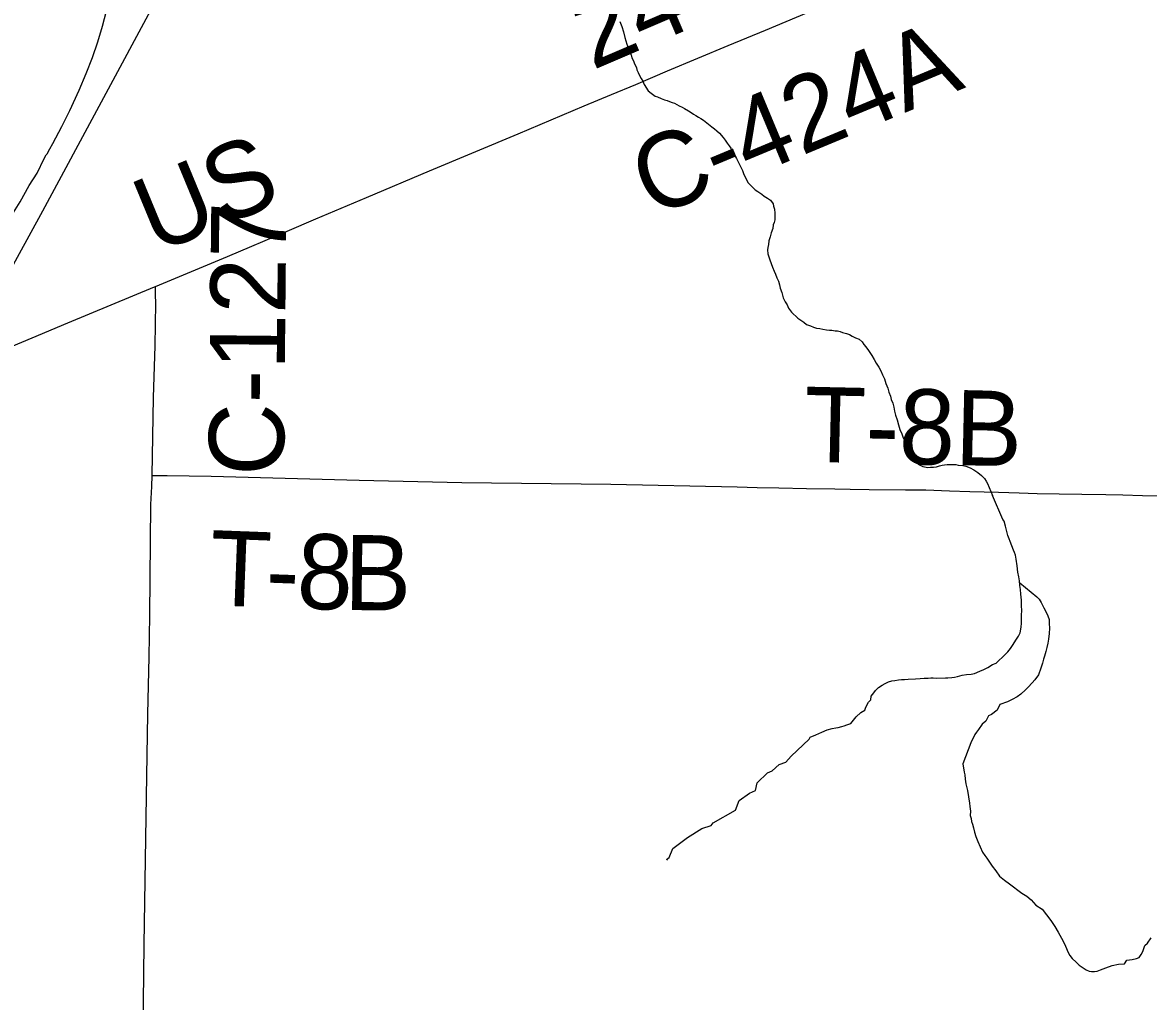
# Model space of a CAD drawing. Extents: x 2.1 to 73.9, y 4 to 26.
# Drawn here: x 44.0631 to 44.4887, y 21.6606 to 22.0307 of the extents above; entities that cross this region are included whole.
import ezdxf

# ---------------------------------------------------------------- set-up
doc = ezdxf.new("R2010")
doc.units = 0
for name, color, linetype in [('GM_X_County_Road', 7, 'Continuous'), ('GM_X_County_Road_Text', 7, 'Continuous'), ('GM_X_Minor_River', 7, 'Continuous'), ('GM_X_Rail_Line', 7, 'Continuous'), ('GM_X_Township_Road', 7, 'Continuous'), ('GM_X_Township_Road_Text', 7, 'Continuous'), ('GM_X_US_Route', 7, 'Continuous')]:
    doc.layers.add(name, color=color, linetype=linetype)

msp = doc.modelspace()

# ---------------------------------------------------------------- linework, layer by layer
at = {"layer": 'GM_X_County_Road'}
for points in [[(44.11329, 21.93085), (44.1405, 21.94215), (44.16309, 21.95176), (44.17395, 21.9564), (44.19313, 21.96454), (44.21691, 21.97456), (44.25046, 21.9886), (44.27537, 21.99911), (44.28569, 22.00344), (44.29488, 22.00725), (44.3069, 22.01234), (44.32983, 22.02197), (44.3439, 22.02781), (44.36339, 22.03597), (44.382, 22.04385), (44.41728, 22.0586), (44.42762, 22.06286), (44.45106, 22.07288), (44.48515, 22.08724), (44.51755, 22.10081), (44.53217, 22.10694), (44.55134, 22.11508), (44.61158, 22.14023), (44.62022, 22.1439)], [(44.02324, 21.90284), (44.02578, 21.90025), (44.02911, 21.89932), (44.03255, 21.89869), (44.03651, 21.89932), (44.03954, 21.89995), (44.055, 21.90649), (44.06674, 21.91144), (44.0802, 21.91713), (44.11294, 21.93071), (44.11329, 21.93085)], [(44.11201, 21.85939), (44.11262, 21.88892), (44.11315, 21.90847), (44.11347, 21.92461), (44.11338, 21.92775), (44.11329, 21.93085)], [(44.10393, 21.3377), (44.10403, 21.34329), (44.10477, 21.39925), (44.10542, 21.4381), (44.10597, 21.48473), (44.10688, 21.54067), (44.10737, 21.57021), (44.10789, 21.60595), (44.10825, 21.63082), (44.10862, 21.64946), (44.10908, 21.6821), (44.10984, 21.73028), (44.11043, 21.76913), (44.11092, 21.79089), (44.1112, 21.80643), (44.11141, 21.8344), (44.11162, 21.84839), (44.11188, 21.8553), (44.11201, 21.85939)]]:
    msp.add_lwpolyline(points, dxfattribs=at)
at = {"layer": 'GM_X_Minor_River'}
for points in [[(44.28889, 22.0311), (44.28962, 22.02919), (44.29016, 22.02709), (44.2907, 22.02499), (44.29142, 22.02251), (44.29197, 22.02117), (44.29252, 22.01964), (44.29307, 22.01849), (44.29343, 22.01735), (44.29398, 22.0162), (44.29435, 22.01505), (44.29508, 22.01371), (44.29526, 22.01276), (44.29582, 22.0118), (44.29618, 22.01084), (44.29692, 22.0095), (44.29748, 22.00854), (44.29803, 22.0072), (44.29951, 22.0049), (44.30064, 22.00393), (44.30214, 22.00277), (44.30309, 22.00256), (44.30441, 22.00197), (44.30573, 22.00138), (44.30668, 22.00118), (44.30762, 22.00078), (44.30857, 22.00039), (44.30952, 22.00018), (44.31121, 21.9992), (44.31235, 21.99861), (44.31329, 21.99822), (44.3148, 21.99725), (44.31574, 21.99666), (44.31668, 21.99608), (44.31762, 21.99549), (44.31856, 21.99491), (44.3195, 21.99432), (44.32045, 21.99373), (44.32232, 21.99219), (44.32364, 21.99121), (44.32458, 21.99044), (44.32552, 21.98966), (44.32646, 21.98889), (44.32795, 21.98716), (44.3287, 21.98619), (44.32944, 21.98504), (44.33018, 21.98408), (44.33074, 21.98312), (44.33129, 21.98197), (44.33203, 21.98082), (44.33296, 21.97928), (44.3337, 21.97775), (44.33444, 21.97622), (44.33517, 21.97469), (44.33572, 21.97316), (44.33738, 21.97009), (44.33888, 21.96855), (44.34, 21.96739), (44.34094, 21.96681), (44.34245, 21.96583), (44.34339, 21.96506), (44.34471, 21.96428), (44.34584, 21.9635), (44.34677, 21.96215), (44.34694, 21.9612), (44.3473, 21.96006), (44.34747, 21.95853), (44.34745, 21.9572), (44.34743, 21.95606), (44.34723, 21.95512), (44.34683, 21.95417), (44.34662, 21.95285), (44.34602, 21.95115), (44.34562, 21.94963), (44.34521, 21.94812), (44.345, 21.94679), (44.3448, 21.94566), (44.34459, 21.94471), (44.34476, 21.94319), (44.34512, 21.94204), (44.34548, 21.94089), (44.34603, 21.93955), (44.34658, 21.93822), (44.34713, 21.93669), (44.34768, 21.93554), (44.34823, 21.9342), (44.34878, 21.93286), (44.34914, 21.93153), (44.3495, 21.93019), (44.35005, 21.92866), (44.35058, 21.92656), (44.35132, 21.92503)], [(44.35132, 21.92503), (44.35206, 21.92388), (44.35261, 21.92273), (44.35373, 21.92119), (44.35617, 21.91887), (44.3573, 21.91809), (44.35842, 21.91732), (44.35936, 21.91654), (44.36088, 21.91595), (44.36201, 21.91555), (44.36315, 21.91515), (44.36447, 21.91494), (44.36561, 21.91473), (44.36694, 21.91452), (44.36808, 21.91431), (44.36903, 21.9143), (44.37017, 21.91409), (44.37112, 21.91407), (44.37206, 21.91387), (44.37301, 21.91347), (44.37452, 21.91307), (44.37566, 21.91267), (44.3766, 21.91209), (44.37792, 21.9115), (44.37924, 21.9109), (44.38037, 21.90994), (44.38112, 21.90897), (44.38186, 21.90801), (44.38279, 21.90667), (44.38409, 21.90475), (44.38502, 21.90321), (44.38576, 21.90187), (44.38669, 21.90034), (44.38743, 21.89899), (44.38816, 21.89746), (44.3889, 21.89593), (44.38944, 21.89421), (44.39018, 21.89249), (44.39053, 21.89096), (44.39108, 21.88944), (44.39144, 21.8881), (44.39199, 21.88676), (44.39234, 21.88523), (44.3927, 21.88371), (44.39306, 21.88218), (44.3936, 21.88046), (44.39414, 21.87856), (44.39469, 21.87684), (44.39542, 21.87512), (44.39597, 21.87359), (44.39652, 21.87244), (44.39707, 21.87148), (44.39873, 21.86803), (44.39947, 21.86688), (44.40003, 21.86573), (44.40114, 21.8642), (44.40208, 21.86342), (44.4034, 21.86283), (44.4053, 21.86242), (44.40625, 21.86259), (44.40739, 21.86257), (44.40854, 21.86275), (44.40968, 21.86311), (44.41064, 21.86328), (44.41159, 21.86346), (44.41255, 21.86363), (44.41369, 21.86361), (44.41464, 21.8636), (44.41578, 21.86358), (44.41673, 21.86338), (44.41843, 21.86316), (44.41957, 21.86295), (44.42127, 21.86235), (44.42259, 21.86157), (44.4241, 21.8606), (44.4256, 21.85943), (44.42673, 21.85828), (44.42728, 21.85732), (44.42784, 21.85636), (44.42972, 21.85187)], [(44.3604, 21.7597), (44.36081, 21.76045), (44.36292, 21.76134), (44.36524, 21.76241), (44.36717, 21.7633), (44.36908, 21.76382), (44.37042, 21.76397), (44.37138, 21.76413), (44.37272, 21.76447), (44.37368, 21.76483), (44.37464, 21.76518), (44.37618, 21.7657), (44.37815, 21.76812), (44.37991, 21.76978), (44.38146, 21.77068), (44.38187, 21.77181), (44.38288, 21.77368), (44.38366, 21.77461), (44.38389, 21.77594), (44.38488, 21.77724), (44.38548, 21.77817), (44.38665, 21.77928), (44.38801, 21.78019), (44.38917, 21.78073), (44.39033, 21.78145), (44.39167, 21.78179), (44.39282, 21.78195), (44.39415, 21.7821), (44.3953, 21.78226), (44.39644, 21.78223), (44.39778, 21.78238), (44.40063, 21.78248), (44.40235, 21.78262), (44.40387, 21.78277), (44.40539, 21.78273), (44.40635, 21.78289), (44.4073, 21.78286), (44.40863, 21.78282), (44.41187, 21.78292), (44.41282, 21.78289), (44.41434, 21.78304), (44.4153, 21.7832), (44.41644, 21.78336), (44.41817, 21.78388), (44.41989, 21.78421), (44.42161, 21.78435), (44.42294, 21.7845), (44.42487, 21.78539), (44.42641, 21.78611), (44.42796, 21.78683), (44.4297, 21.78792), (44.43105, 21.78845), (44.43222, 21.78955), (44.43339, 21.79066), (44.43437, 21.79158), (44.43555, 21.79269), (44.43653, 21.79399), (44.43753, 21.79548), (44.43853, 21.79717), (44.43952, 21.79866), (44.44013, 21.79997), (44.44057, 21.80205), (44.44062, 21.80357), (44.44065, 21.80471), (44.44068, 21.80566), (44.44071, 21.8068), (44.44075, 21.80813), (44.44063, 21.81041), (44.44068, 21.81231), (44.44037, 21.8146), (44.44023, 21.81632), (44.44008, 21.81784), (44.43994, 21.81956), (44.43961, 21.82109), (44.43928, 21.82281), (44.43897, 21.82529), (44.43866, 21.82777), (44.43833, 21.8293), (44.43797, 21.83026), (44.43762, 21.83122), (44.43639, 21.83449), (44.43603, 21.83545), (44.4355, 21.83679), (44.43465, 21.84024), (44.43414, 21.84216), (44.43358, 21.84274), (44.42972, 21.85187)], [(44.44001, 21.81877), (44.44642, 21.81348), (44.44735, 21.81269), (44.44807, 21.81134), (44.44862, 21.81037), (44.44916, 21.8094), (44.45005, 21.80748), (44.45059, 21.80632), (44.45112, 21.80497), (44.45108, 21.80346), (44.45122, 21.80174), (44.45116, 21.79965), (44.4509, 21.79757), (44.45067, 21.79605), (44.45024, 21.79435), (44.44982, 21.79285), (44.44938, 21.79115), (44.44897, 21.79002), (44.44855, 21.78851), (44.44792, 21.78663), (44.44708, 21.78399), (44.4457, 21.78213), (44.44471, 21.78102), (44.44314, 21.77935), (44.44217, 21.77843), (44.44041, 21.77677), (44.43904, 21.77567), (44.43711, 21.77477), (44.43538, 21.77387), (44.43249, 21.77282), (44.43148, 21.77075), (44.42934, 21.76911), (44.42818, 21.76857), (44.42717, 21.76651), (44.42581, 21.76541), (44.42442, 21.76336), (44.42363, 21.76243), (44.42303, 21.76149), (44.42146, 21.75831)], [(44.30686, 21.71403), (44.30648, 21.71423), (44.30745, 21.71497), (44.30886, 21.71836), (44.31447, 21.7226), (44.31986, 21.7259), (44.32332, 21.72715), (44.3241, 21.72808), (44.33257, 21.73283), (44.33398, 21.7366), (44.33785, 21.73936), (44.34015, 21.74026), (44.34079, 21.74328), (44.34467, 21.74699), (44.3464, 21.74771), (44.34912, 21.75012), (44.35161, 21.75102), (44.35356, 21.75325), (44.3604, 21.7597)], [(44.42146, 21.75831), (44.41851, 21.75046), (44.41901, 21.74722), (44.41918, 21.74627), (44.41933, 21.74455), (44.41967, 21.74284), (44.42019, 21.74035), (44.42103, 21.73559), (44.42119, 21.73425), (44.42134, 21.73254), (44.4213, 21.73083), (44.42166, 21.72968), (44.42182, 21.72854), (44.42218, 21.72758), (44.42253, 21.72624), (44.42287, 21.72453), (44.42341, 21.72299), (44.42413, 21.72108), (44.42503, 21.71897), (44.42594, 21.71705), (44.42686, 21.7157), (44.4276, 21.71473), (44.42851, 21.71319), (44.42962, 21.71165), (44.43091, 21.70991), (44.43239, 21.70797), (44.43425, 21.70641), (44.43612, 21.70504), (44.43762, 21.70387), (44.4393, 21.70269), (44.4408, 21.70152), (44.44267, 21.70034), (44.44435, 21.69897), (44.44602, 21.69703), (44.44846, 21.69546), (44.45012, 21.69333), (44.45178, 21.6912), (44.45325, 21.68889), (44.45453, 21.68677), (44.45581, 21.68446), (44.45691, 21.68235), (44.45763, 21.68062), (44.45817, 21.67928), (44.4589, 21.67793), (44.45982, 21.67677), (44.46131, 21.67541), (44.46243, 21.67425), (44.46393, 21.67326), (44.46505, 21.67248), (44.46618, 21.67207), (44.46713, 21.67186), (44.46827, 21.67183), (44.46922, 21.672), (44.47056, 21.67254), (44.47248, 21.67326), (44.47497, 21.67415), (44.47727, 21.67467), (44.47955, 21.67481), (44.48053, 21.67612), (44.48244, 21.67645), (44.48416, 21.6768), (44.48512, 21.67715), (44.4859, 21.67828), (44.4865, 21.6794), (44.48731, 21.68166), (44.48828, 21.68259), (44.48966, 21.68465)]]:
    msp.add_lwpolyline(points, dxfattribs=at)
at = {"layer": 'GM_X_Rail_Line'}
msp.add_lwpolyline([(44.01624, 21.85997), (44.07076, 21.95948), (44.11421, 22.04032), (44.14593, 22.09204), (44.16895, 22.13725), (44.18025, 22.17245), (44.18677, 22.20331), (44.19155, 22.24113), (44.20241, 22.39195), (44.23022, 22.73533), (44.25279, 22.99625)], dxfattribs=at)
at = {"layer": 'GM_X_Township_Road'}
msp.add_lwpolyline([(44.11201, 21.85939), (44.11776, 21.85942), (44.13438, 21.85913), (44.19029, 21.85767), (44.22912, 21.85677), (44.28548, 21.85612), (44.33322, 21.85509), (44.34076, 21.85493), (44.34888, 21.85476), (44.35936, 21.85454), (44.37016, 21.85431), (44.37594, 21.85426), (44.38305, 21.85418), (44.39684, 21.85405), (44.40454, 21.85397), (44.41341, 21.85367), (44.42111, 21.85341), (44.43197, 21.85305), (44.43983, 21.85282), (44.44661, 21.85263), (44.45495, 21.85244), (44.46345, 21.85232), (44.47259, 21.85219), (44.4789, 21.8521), (44.48644, 21.85186), (44.49248, 21.85167)], dxfattribs=at)
at = {"layer": 'GM_X_US_Route'}
for points in [[(44.07232, 21.98108), (44.07339, 21.98295), (44.07454, 21.98496), (44.07789, 21.9913), (44.08091, 21.99745), (44.08444, 22.00508), (44.08715, 22.01138), (44.08951, 22.01748), (44.09154, 22.02338), (44.09334, 22.02935), (44.09485, 22.03507)], [(43.98106, 21.86319), (43.98963, 21.8714), (43.9987, 21.87953), (44.00953, 21.88973), (44.02324, 21.90284), (44.02619, 21.90682), (44.03213, 21.91421), (44.03734, 21.92161), (44.04119, 21.92765), (44.04526, 21.93421), (44.04932, 21.94119), (44.05359, 21.94817), (44.05776, 21.95577), (44.06213, 21.96285), (44.06557, 21.969), (44.06859, 21.97369), (44.07129, 21.97928), (44.07205, 21.98061), (44.07232, 21.98108)]]:
    msp.add_lwpolyline(points, dxfattribs=at)

# ---------------------------------------------------------------- texts
at = {"layer": 'GM_X_County_Road_Text'}
for s, rotation, p in [('24', 23.1986, (44.27846, 22.01254)), ('C-424A', 22.62, (44.30099, 21.95668)), ('US', 22.4968, (44.11318, 21.94301)), ('C-127', 89.4474, (44.16182, 21.85917))]:
    msp.add_text(s, height=0.028409, rotation=rotation, dxfattribs=at).set_placement(p)
at = {"layer": 'GM_X_Township_Road_Text'}
for s, height, rotation, p in [('T-8B', 0.028409, 358.7491, (44.3583, 21.86461)), ('T', 0.02841, 357.8396, (44.13337, 21.81039)), ('8', 0.02841, 358.185, (44.16645, 21.80916)), ('B', 0.02841, 359.2207, (44.1845, 21.80859)), ('-', 0.02841, 357.9084, (44.15464, 21.80959))]:
    msp.add_text(s, height=height, rotation=rotation, dxfattribs=at).set_placement(p)

doc.saveas('drawing.dxf')
